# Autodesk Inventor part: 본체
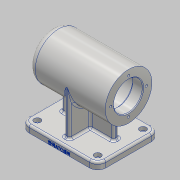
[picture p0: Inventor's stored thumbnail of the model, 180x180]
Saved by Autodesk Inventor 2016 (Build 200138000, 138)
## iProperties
Created: 2020-10
Part Number: 본체
Material: 알루미늄 6061
Document SubType Name: Modeling
Designer: 605-17
Density: 2.7 g/cm^3
Appearance: 알루미늄 - 평지
Mass: 1026.24 g
Surface Area: 757.016 cm^2
Volume: 380.088 cm^3
Author: 605-17
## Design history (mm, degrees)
sketch "스케치1"
  geometry: L1 (56, -45)-(-56, -45); L2 (-56, -45)-(-56, 45); L3 (-56, 45)-(56, 45); L4 (56, 45)-(56, -45); L5 (56, -45)-(-56, 45); L6 (-56, -45)-(56, 45); 1 further point
  constraints: 12 end point, 2 midpoint, 2 parallel, 1 horizontal, 1 perpendicular
  dimensions: "d0" = 112 distance of L2.end L3.end; "d1" = 90 distance of L1.end L2.end
extrude "돌출1" new body sketch "스케치1" distance "d2" = 10; taper "d3" = 0 deg
sketch "스케치2"
  geometry: L1 (56, 74)-(-56, 74); L2 (56, 0)-(-56, 0) reference; L3 (56, 74)-(56, 108); L4 (56, 108)-(-56, 108); L5 (-56, 108)-(-56, 74); L6 (50, 74)-(50, 84.5); L7 (50, 84.5)-(47, 84.5); L8 (47, 84.5)-(47, 90); L9 (47, 90)-(43, 90); L10 (43, 90)-(43, 91.5); L11 (43, 91.5)-(25, 91.5); L12 (25, 91.5)-(25, 95); L13 (25, 95)-(13, 95); L14 (13, 95)-(13, 98); L15 (13, 98)-(-41, 98); L16 (-41, 98)-(-41, 95); L17 (-41, 95)-(-56, 95); 2 further points
  constraints: 32 end point, 12 perpendicular, 2 point on line, 2 vertical, 1 horizontal, 1 midpoint, 1 parallel, 1 vertical alignment
  dimensions: "d4" = 74 distance between parallel lines of L2 L1; "d5" = 3 distance between parallel lines of L8 L6; "d6" = 4 distance between parallel lines of L10 L8; "d7" = 18 distance between parallel lines of L12 L10; "d8" = 12 distance between parallel lines of L14 L12; "d9" = 15 distance between parallel lines of L5 L16; "d10" = 54 distance between parallel lines of L16 L14; "d11" = 112 distance between parallel lines of L5 L3; "d12" = 21 diameter of L7 L1; "d13" = 32 diameter of L9 L1; "d14" = 35 diameter of L11 L1; "d15" = 42 diameter of L13 L1; "d16" = 48 diameter of L15 L1; "d17" = 42 diameter of L17 L1; "d18" = 68 diameter of L4 L1
revolve "회전1" sketch "스케치2" stored, may be unused: angle "d19" = 90 deg
node "작업 평면1"
sketch "스케치3"
  geometry: L1 (4, -34)-(-4, -34); L2 (-4, -34)-(-4, 34); L3 (-4, 34)-(4, 34); L4 (4, 34)-(4, -34); L5 (4, -34)-(-4, 34); L6 (-4, -34)-(4, 34); 1 further point
  constraints: 12 end point, 2 midpoint, 2 parallel, 1 horizontal, 1 perpendicular
  dimensions: "d21" = 68 distance of L3.end L1.start; "d22" = 8 distance of L2.end L3.end
extrude "돌출2" join sketch "스케치3" stored distance "d23" = 10; taper "d24" = 0 deg
sketch "스케치5"
  geometry: L1 (-4, 10)-(-4, 74) reference; L2 (-56, 40)-(56, 40) reference; L3 (-56, 10)-(56, 10) reference; L4 (-38, 40)-(-38, 10); 1 further point
  constraints: 2 end point, 2 point on line, 1 vertical
  dimensions: "d35" = 18 distance of L3.start L4.end
feature "리브2" sketch "스케치5" dims "d36" = 1, "d37" = 8, "d38" = 0, "d39" = 0, "d40" = 1, "d41" = 1
sketch "스케치6"
  geometry: C1 r 34 at (0, 0) reference; 2 further points
  constraints: 1 horizontal alignment
  dimensions: "d42" = 26 distance of C1.centre point (-26, 0)
hole "구멍1" sketch "스케치6" at (-26, 0) diameter "d43" = 3.242; stored, may be unused: countersink angle "d47" = 90 deg, drill point angle "d49" = 118 deg; dims "d44" = 8, "d45" = 4, "d46" = 2, "d48" = 11
fillet "모깎기1" dims "d53" = 3, "d54" = 0.3, "d55" = 10
chamfer "모따기1" distance "d56" = 1; stored, may be unused: second distance "d57" = 2, angle "d58" = 45 deg
fillet "모깎기2" dims "d59" = 12
hole "구멍2" diameter "d63" = 5.5; stored, may be unused: countersink angle "d67" = 90 deg, drill point angle "d69" = 118 deg; dims "d64" = 8, "d65" = 9.5, "d66" = 5.4, "d68" = 11, "d70" = 10, "d71" = 10
hole "구멍3" diameter "d74" = 5.5; stored, may be unused: countersink angle "d78" = 90 deg, drill point angle "d80" = 118 deg; dims "d72" = 10, "d73" = 10, "d75" = 8, "d76" = 9.5, "d77" = 5.4, "d79" = 11
fillet "모깎기4" dims "d81" = 3
fillet "모깎기5" dims "d82" = 3
fillet "모깎기6" dims "d83" = 3
fillet "모깎기7" dims "d84" = 3
sketch "스케치8"
  geometry: L1 (25.59, 5.624)-(62.41, 5.624); L2 (62.41, 5.624)-(62.41, 0.376); L3 (62.41, 0.376)-(25.59, 0.376); L4 (25.59, 0.376)-(25.59, 5.624); L5 (44, 5.624)-(44, 0.376); L6 (44, 3)-(25.59, 3); L7 (100, 0)-(100, 7) reference; 1 further point
  constraints: 4 end point, 4 midpoint, 2 other
  dimensions: "d85" = 56 distance from line of L7 L5.end; "d86" = 3 vertical distance of L7.start L6.start
feature "엠보싱1" sketch "스케치8" dims "d0" = 112, "d1" = 90, "d87" = 0.5, "d88" = 0
node "솔리드1"
mirror "대칭1"
pattern_circular "원형 패턴1" dims angle "d51" = 360 deg
mirror "대칭2"
